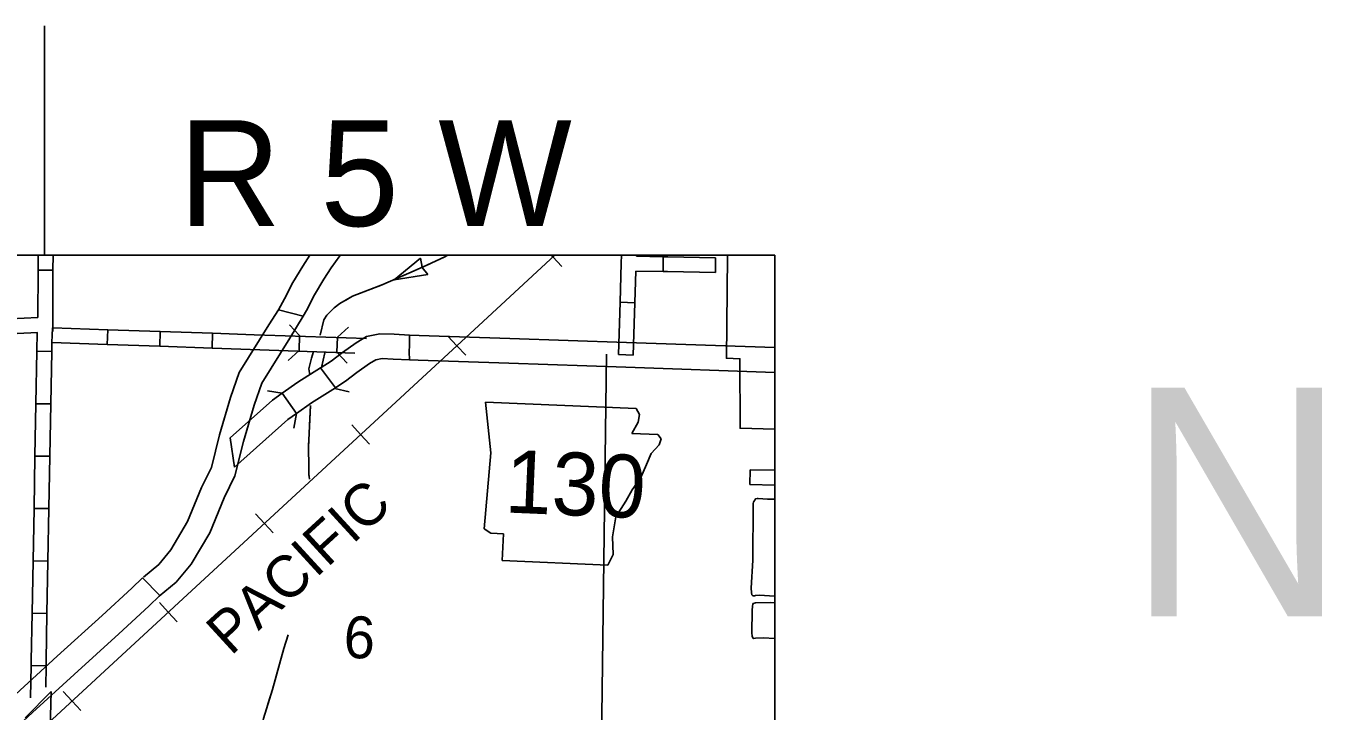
# Model space of a CAD drawing. Extents: x 1196286 to 1268366, y 2040822 to 2082115.
# Drawn here: x 1238759 to 1243659, y 2063873 to 2066463 of the extents above; entities that cross this region are included whole.
import ezdxf

# ---------------------------------------------------------------- set-up
doc = ezdxf.new("R2010")
doc.units = 0
for name, color, linetype in [('26', 7, 'Continuous'), ('60', 7, 'Continuous'), ('61', 7, 'Continuous'), ('62', 7, 'Continuous'), ('63', 7, 'Continuous'), ('Level 1', 7, 'Continuous'), ('Level 69', 7, 'Continuous'), ('Level 76', 7, 'Continuous'), ('Level 78', 7, 'Continuous'), ('Level 8', 7, 'Continuous'), ('Level 81', 7, 'Continuous'), ('Level 83', 7, 'Continuous'), ('Level 84', 7, 'Continuous'), ('Level 87', 7, 'Continuous')]:
    doc.layers.add(name, color=color, linetype=linetype)

msp = doc.modelspace()

# ---------------------------------------------------------------- linework, layer by layer
at = {"layer": '60'}
msp.add_lwpolyline([(1240928, 2063270.6), (1240953.2, 2065222)], dxfattribs=at)
at = {"layer": '61'}
for p, q in [((1241168.3, 2065590.8), (1241167.2, 2065534.5)), ((1241366.3, 2065587), (1241365.2, 2065530.8)), ((1238804, 2065360.9), (1238804.6, 2065539.9)), ((1238804.6, 2065539.9), (1238860.9, 2065539.7)), ((1241060.9, 2065416.5), (1241004.7, 2065418.3)), ((1238639.5, 2065352.5), (1238804, 2065360.9)), ((1238642.3, 2065296.3), (1238802.5, 2065304.5)), ((1238858.9, 2065322.1), (1238856.9, 2065265.9)), ((1239068.4, 2065314.9), (1239066.4, 2065258.7)), ((1239266.2, 2065308.1), (1239264.3, 2065251.9)), ((1239464.1, 2065301.3), (1239462.2, 2065245.1)), ((1239793.5, 2065292.3), (1239791.6, 2065236.1)), ((1239936.5, 2065286.1), (1239934.6, 2065229.9)), ((1238856.3, 2065232.1), (1238800.1, 2065233.1)), ((1241054.6, 2065218.6), (1240998.4, 2065220.4)), ((1238852.7, 2065034.1), (1238796.5, 2065035.1)), ((1238849.1, 2064836.1), (1238792.9, 2064837.1)), ((1238845.5, 2064638.2), (1238789.3, 2064639.2)), ((1238841.9, 2064440.2), (1238785.7, 2064441.2)), ((1238838.3, 2064242.2), (1238782.1, 2064243.2)), ((1238834.7, 2064044.3), (1238778.5, 2064045.3))]:
    msp.add_line(p, q, dxfattribs=at)
for points in [[(1238804.6, 2065539.9), (1238804.8, 2065596.8)], [(1238860.9, 2065539.7), (1238861.1, 2065596.8)], [(1241004.7, 2065418.3), (1241009.3, 2065566), (1241010.3, 2065596.8)], [(1241066.5, 2065592.7), (1241066.6, 2065596.8)], [(1241168.3, 2065590.8), (1241066.5, 2065592.7)], [(1241366.3, 2065587), (1241184.9, 2065590.4), (1241168.3, 2065590.8)], [(1238860.2, 2065341.7), (1238860.9, 2065539.7)], [(1241054.6, 2065218.6), (1241064.7, 2065536.4)], [(1241167.2, 2065534.5), (1241064.7, 2065536.4)], [(1241365.2, 2065530.8), (1241183.9, 2065534.2), (1241167.2, 2065534.5)], [(1240998.4, 2065220.4), (1241004.7, 2065418.3)], [(1238860.1, 2065307.5), (1238860.2, 2065341.7)], [(1238800.1, 2065233.1), (1238801.4, 2065304.5)], [(1239068.4, 2065314.9), (1238860.1, 2065322.1)], [(1239266.2, 2065308.1), (1239068.4, 2065314.9)], [(1239464.1, 2065301.3), (1239266.2, 2065308.1)], [(1239662, 2065294.5), (1239621.3, 2065295.9), (1239464.1, 2065301.3)], [(1240045.9, 2065281.3), (1239662, 2065294.5)], [(1238796.5, 2065035.1), (1238800.1, 2065233.1)], [(1238856.3, 2065232.1), (1238856.9, 2065265.9)], [(1239066.4, 2065258.7), (1238856.9, 2065265.9)], [(1239264.3, 2065251.9), (1239066.4, 2065258.7)], [(1239462.2, 2065245.1), (1239264.3, 2065251.9)], [(1240001.7, 2065226.6), (1239462.2, 2065245.1)], [(1238852.7, 2065034.1), (1238856.3, 2065232.1)], [(1238792.9, 2064837.1), (1238796.5, 2065035.1)], [(1238849.1, 2064836.1), (1238852.7, 2065034.1)], [(1238789.3, 2064639.2), (1238792.9, 2064837.1)], [(1238845.5, 2064638.2), (1238849.1, 2064836.1)], [(1238785.7, 2064441.2), (1238789.3, 2064639.2)], [(1238841.9, 2064440.2), (1238845.5, 2064638.2)], [(1238782.1, 2064243.2), (1238785.7, 2064441.2)], [(1238838.3, 2064242.2), (1238841.9, 2064440.2)], [(1238778.5, 2064045.3), (1238778.8, 2064063.5), (1238782.1, 2064243.2)], [(1238834.7, 2064044.3), (1238835.1, 2064062.5), (1238838.3, 2064242.2)], [(1238776.3, 2063922.8), (1238778.5, 2064045.3)], [(1238833.3, 2063963), (1238834.7, 2064044.3)]]:
    msp.add_lwpolyline(points, dxfattribs=at)
at = {"layer": '62'}
for points in [[(1240353.1, 2065596.8), (1240340.4, 2065589.5), (1240260.6, 2065552.4), (1240206.7, 2065528.5), (1240108.1, 2065485.6), (1239993.7, 2065441.3), (1239945.4, 2065413.6), (1239923.8, 2065397.5), (1239905.8, 2065380.3), (1239896, 2065369.2), (1239884.5, 2065352.2), (1239871.2, 2065293.5)], [(1240353.1, 2065596.8), (1240340.4, 2065589.5), (1240260.6, 2065552.4), (1240206.7, 2065528.5), (1240108.1, 2065485.6), (1239993.7, 2065441.3), (1239945.4, 2065413.6), (1239923.8, 2065397.5), (1239905.8, 2065380.3), (1239896, 2065369.2), (1239884.5, 2065352.2), (1239871.2, 2065293.5)], [(1240353.1, 2065596.8), (1240340.4, 2065589.5), (1240331.2, 2065585.2)], [(1240286.3, 2065564.4), (1240260.6, 2065552.4), (1240206.7, 2065528.5), (1240150.6, 2065504.1)], [(1240105.2, 2065484.5), (1240035.9, 2065457.7)], [(1240035.9, 2065457.7), (1239993.7, 2065441.3), (1239968.6, 2065426.9)], [(1239927.2, 2065400), (1239923.8, 2065397.5), (1239905.8, 2065380.3), (1239896, 2065369.2), (1239884.5, 2065352.2), (1239871.2, 2065293.5)], [(1239845.9, 2065231.9), (1239838.4, 2065207.6), (1239828.6, 2065167.4), (1239831.6, 2065144.4)], [(1239833.9, 2065028.3), (1239827.2, 2064870.9), (1239828.8, 2064795.9), (1239827.7, 2064769.5), (1239830.5, 2064749.4)], [(1239833.9, 2065028.3), (1239827.2, 2064870.9), (1239828.8, 2064795.9), (1239827.7, 2064769.5), (1239830.5, 2064749.4)], [(1239833.9, 2065028.3), (1239830.8, 2064954.1)], [(1239828.6, 2064904.6), (1239827.2, 2064870.9), (1239828.8, 2064795.9), (1239827.7, 2064769.5), (1239829.5, 2064756.3)], [(1241590.6, 2064306.8), (1241531.4, 2064310.8), (1241517.1, 2064309.8), (1241512.6, 2064308.7), (1241507.4, 2064308.8), (1241502.6, 2064312.6), (1241501.2, 2064320.9), (1241500.6, 2064337.4), (1241506.3, 2064443.5), (1241508.2, 2064652.2), (1241508.6, 2064657.5), (1241509.4, 2064662.4), (1241510.6, 2064665.3), (1241514, 2064670.2), (1241517.4, 2064675.4), (1241523.1, 2064676.5), (1241527.6, 2064677.2), (1241562.8, 2064674.6), (1241590.6, 2064673.8)], [(1241590.6, 2064147.9), (1241545.7, 2064150.4), (1241516.5, 2064148.4), (1241510.9, 2064147.7), (1241507.5, 2064148.5), (1241504.9, 2064155.3), (1241503.6, 2064169.6), (1241504.9, 2064251.6), (1241505.5, 2064271.2), (1241506.3, 2064276.1), (1241508.2, 2064279.8), (1241516.5, 2064282.3), (1241575.3, 2064283.2), (1241590.6, 2064282)], [(1239749.7, 2064160.6), (1239733.5, 2064109.1), (1239690.6, 2063954.2), (1239656.8, 2063845.1), (1239646.5, 2063801.2), (1239642.1, 2063772.6), (1239638.1, 2063749.3), (1239633.2, 2063710.3), (1239613.6, 2063468.2), (1239606, 2063290.9)], [(1239749.7, 2064160.6), (1239733.5, 2064109.1), (1239690.6, 2063954.2), (1239656.8, 2063845.1), (1239646.5, 2063801.2), (1239642.1, 2063772.6), (1239638.1, 2063749.3), (1239633.2, 2063710.3), (1239613.6, 2063468.2), (1239606, 2063290.9)], [(1239749.7, 2064160.6), (1239733.5, 2064109.1), (1239728.1, 2064089.6)], [(1239714.9, 2064041.9), (1239690.6, 2063954.2), (1239673.6, 2063899.3)]]:
    msp.add_lwpolyline(points, dxfattribs=at)
at = {"layer": '63'}
for p, q in [((1240250.9, 2065584.6), (1240150.8, 2065503.7)), ((1240256.2, 2065550.7), (1240250.9, 2065584.6)), ((1240256.4, 2065550.3), (1240256.2, 2065550.7)), ((1240277.9, 2065523.7), (1240256.4, 2065550.3)), ((1240150.8, 2065503.7), (1240277.9, 2065523.7))]:
    msp.add_line(p, q, dxfattribs=at)
at = {"layer": 'Level 1'}
msp.add_lwpolyline([(1241590.6, 2064938.5), (1241458.4, 2064942.2), (1241458.3, 2065204.9), (1241407, 2065206.6), (1241411.5, 2065591.9), (1241411.7, 2065596.8)], dxfattribs=at)
at = {"layer": 'Level 69'}
msp.add_line((1241495.4, 2064729.2), (1241496.4, 2064785.5), dxfattribs=at)
for points in [[(1241496.4, 2064785.5), (1241590.6, 2064783.9)], [(1241495.4, 2064729.2), (1241590.6, 2064727.6)]]:
    msp.add_lwpolyline(points, dxfattribs=at)
at = {"layer": 'Level 76'}
for points in [[(1239876.1, 2065172.3), (1239888.6, 2065227.2)], [(1239980.7, 2065080.4), (1239925.9, 2065092.9)], [(1239671.7, 2065084), (1239727.1, 2065074.4)], [(1239781.1, 2064997.7), (1239771.4, 2064942.3)]]:
    msp.add_lwpolyline(points, dxfattribs=at)
at = {"layer": 'Level 78'}
for p, q in [((1240496, 2065041.2), (1240516.4, 2064849.8)), ((1241078.2, 2064994.1), (1241066, 2065016.5)), ((1241073.8, 2064965.7), (1241078.2, 2064994.1)), ((1241049.8, 2064922.3), (1241073.8, 2064965.7)), ((1241148, 2064918.1), (1241049.8, 2064922.3)), ((1241160, 2064901.7), (1241148, 2064918.1)), ((1241152.7, 2064879.7), (1241160, 2064901.7)), ((1240516.4, 2064849.8), (1240491.4, 2064562)), ((1241105.1, 2064805.6), (1241122.7, 2064846.1)), ((1241122.7, 2064846.1), (1241152.7, 2064879.7)), ((1241083.9, 2064755.7), (1241105.1, 2064805.6)), ((1241050.2, 2064709.5), (1241083.9, 2064755.7)), ((1241026.1, 2064666.1), (1241050.2, 2064709.5)), ((1240988.6, 2064607.4), (1241026.1, 2064666.1)), ((1240975.9, 2064531.7), (1240988.6, 2064607.4)), ((1240491.4, 2064562), (1240516.1, 2064545.1)), ((1240516.1, 2064545.1), (1240563.6, 2064543)), ((1240563.6, 2064543), (1240559.3, 2064441.6)), ((1240979.4, 2064464.9), (1240975.9, 2064531.7)), ((1240958.6, 2064424.5), (1240979.4, 2064464.9)), ((1240559.3, 2064441.6), (1240958.6, 2064424.5))]:
    msp.add_line(p, q, dxfattribs=at)
msp.add_lwpolyline([(1240496, 2065041.2), (1241066, 2065016.5)], dxfattribs=at)
at = {"layer": 'Level 8'}
msp.add_line((1238829.2, 2066463.3), (1238829.2, 2065596.8), dxfattribs=at)
msp.add_lwpolyline([(1241590.6, 2065596.8), (1214332.8, 2065596.8), (1214332.8, 2047966.3), (1241590.6, 2047966.3)], close=True, dxfattribs=at)
at = {"layer": 'Level 81'}
for p, q in [((1240751, 2065590.6), (1240745.2, 2065596.8)), ((1240751, 2065590.6), (1240784.6, 2065554.3)), ((1240387.6, 2065254.4), (1240354.1, 2065290.8)), ((1240387.6, 2065254.4), (1240421.2, 2065218)), ((1240024, 2064918.5), (1239990.5, 2064954.9)), ((1240024, 2064918.5), (1240057.6, 2064882.2)), ((1239660.4, 2064582.6), (1239626.8, 2064619)), ((1239660.4, 2064582.6), (1239694, 2064546.3)), ((1239296.8, 2064246.8), (1239263.2, 2064283.1)), ((1239296.8, 2064246.8), (1239330.4, 2064210.4)), ((1238933.2, 2063910.9), (1238899.6, 2063947.3)), ((1238933.2, 2063910.9), (1238966.8, 2063874.6))]:
    msp.add_line(p, q, dxfattribs=at)
msp.add_lwpolyline([(1240757.7, 2065596.8), (1240486.9, 2065346.1), (1239022.5, 2063993.4), (1236837.6, 2061976.6), (1235905.3, 2061125.6), (1235621.7, 2060865.7), (1235429, 2060684.3)], dxfattribs=at)
msp.add_lwpolyline([(1240757.7, 2065596.8), (1240486.9, 2065346.1), (1239022.5, 2063993.4), (1236837.6, 2061976.6), (1235905.3, 2061125.6), (1235621.7, 2060865.7), (1235429, 2060684.3)], dxfattribs=at)
msp.add_lwpolyline([(1240757.7, 2065596.8), (1240486.9, 2065346.1), (1239022.5, 2063993.4), (1236837.6, 2061976.6), (1235905.3, 2061125.6), (1235621.7, 2060865.7), (1235429, 2060684.3)], dxfattribs=at)
at = {"layer": 'Level 83'}
for points in [[(1239755.1, 2065333.4), (1239793.5, 2065292.3)], [(1239936.5, 2065286.1), (1239977.6, 2065324.5)], [(1239791.6, 2065236.1), (1239750.5, 2065197.7)], [(1239972.9, 2065188.8), (1239934.6, 2065229.9)]]:
    msp.add_lwpolyline(points, dxfattribs=at)
at = {"layer": 'Level 84'}
for p, q in [((1239947.8, 2065596.8), (1239832.4, 2065596.8)), ((1239713.9, 2065389.6), (1239807.2, 2065365.5)), ((1241590.6, 2065153.5), (1241590.6, 2065247.3)), ((1239875.1, 2065171.7), (1239872.7, 2065170.2)), ((1239265.3, 2064309.9), (1239200, 2064377.2))]:
    msp.add_line(p, q, dxfattribs=at)
for points in [[(1239832.4, 2065596.8), (1239805.8, 2065555.1), (1239767.6, 2065493), (1239735.9, 2065431.1), (1239713.9, 2065389.6)], [(1239807.2, 2065365.5), (1239819, 2065387.7), (1239849.4, 2065447), (1239885.2, 2065505.3), (1239912.9, 2065548.6), (1239945.4, 2065593.6), (1239947.8, 2065596.8)], [(1239713.9, 2065389.6), (1239676.5, 2065332.6), (1239564.7, 2065153), (1239532.4, 2065058.5), (1239490.7, 2064917.3), (1239459.8, 2064794.2), (1239422.6, 2064717.7), (1239369.3, 2064589.3), (1239306.4, 2064482.7), (1239260.5, 2064427.1), (1239202.9, 2064379.7)], [(1239807.2, 2065365.5), (1239713.9, 2065389.6)], [(1239262.5, 2064307.3), (1239327, 2064360.4), (1239383.3, 2064428.7), (1239453.4, 2064547.3), (1239508.2, 2064679.2), (1239548.3, 2064761.9), (1239581.1, 2064892.6), (1239621.8, 2065030), (1239650, 2065112.5), (1239755.8, 2065282.7), (1239807.2, 2065365.5)], [(1240209.1, 2065294.7), (1240151.3, 2065297.3), (1240097.2, 2065299.6), (1240046.3, 2065289), (1240006.6, 2065265), (1239954.9, 2065228.3), (1239912.3, 2065196.3), (1239875.1, 2065171.7)], [(1241590.6, 2065247.3), (1241029.3, 2065266.3), (1240587.6, 2065281.5), (1240244.9, 2065293.3), (1240209.1, 2065294.7), (1240209.1, 2065255.7), (1240208, 2065230.8), (1240208.3, 2065201.1), (1240241.6, 2065199.6), (1240584.4, 2065187.8), (1241026.1, 2065172.6), (1241590.6, 2065153.5)], [(1239926.8, 2065093.5), (1239966.3, 2065119.7), (1240010.2, 2065152.6), (1240058, 2065186.6), (1240081.1, 2065200.5), (1240104.9, 2065205.4), (1240147.3, 2065203.6), (1240208.3, 2065201.1)], [(1239872.7, 2065170.2), (1239786.4, 2065116.1), (1239727.1, 2065074.4)], [(1239872.7, 2065170.2), (1239929.2, 2065095)], [(1239929.2, 2065095), (1239838.3, 2065038), (1239781.1, 2064997.7)], [(1239727.1, 2065074.4), (1239690.4, 2065048.5), (1239530.4, 2064906)], [(1239781.1, 2064997.7), (1239727.1, 2065074.4)], [(1239546.9, 2064795.2), (1239748.7, 2064975), (1239781.1, 2064997.7)], [(1239530.4, 2064906), (1239546.9, 2064795.2)], [(1239200, 2064377.2), (1239159, 2064337.3), (1239047, 2064234.7), (1238877.3, 2064081), (1238720.3, 2063936.3), (1238106.7, 2063367.3), (1237029.5, 2062375.5), (1236487.9, 2061877.6)], [(1239200, 2064377.2), (1239265.3, 2064309.9)], [(1236551.3, 2061808.6), (1237092.9, 2062306.5), (1238170.3, 2063298.4), (1238783.9, 2063867.4), (1238940.5, 2064011.8), (1239110.1, 2064165.4), (1239223.3, 2064269.1), (1239265.3, 2064309.9)]]:
    msp.add_lwpolyline(points, dxfattribs=at)
at = {"layer": 'Level 87'}
for p, q in [((1238853.5, 2063946.7), (1238756.2, 2063847.6)), ((1238847.9, 2063735.9), (1238853.5, 2063946.7))]:
    msp.add_line(p, q, dxfattribs=at)

# ---------------------------------------------------------------- texts
at = {"layer": '26'}
msp.add_text('R 5 W', height=400, dxfattribs=at).set_placement((1239336.6, 2065706.7))
at = {"layer": '60'}
msp.add_text('6', height=158.4, rotation=357.548, dxfattribs=at).set_placement((1239957.5, 2064075.1))
at = {"layer": 'Level 78'}
msp.add_text('130', height=237.6, rotation=357.548, dxfattribs=at).set_placement((1240566.4, 2064624))
at = {"layer": 'Level 8'}
msp.add_text('N', height=864, dxfattribs=at).set_placement((1242918.8, 2064231.2))
at = {"layer": 'Level 81'}
msp.add_text('PACIFIC', height=158.4, rotation=42.5465, dxfattribs=at).set_placement((1239533.4, 2064079))

doc.saveas('drawing.dxf')
